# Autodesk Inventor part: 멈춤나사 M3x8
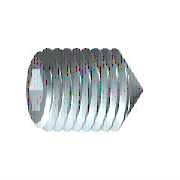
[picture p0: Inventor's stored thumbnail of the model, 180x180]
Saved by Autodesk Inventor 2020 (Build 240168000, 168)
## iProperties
Created: 2012-02
Part Number: 멈춤나사 M3x8
Material: 강철, 연강
Description: 6각 소켓 머리 없는 멈춤 나사
Document SubType Name: Modeling
Standard: KS B 1028
Designer: mduedu
Standards Organization: KS
Language: ko-KR
Size Designation: 원추점 M3x8
Categories: <MemberInstance><Categories><Category DisplayName="조임쇠" InternalName="e4da775c-781d-43d5-af7c-5136215cf5a6" Mnemonic="FSTN"><Category DisplayName="볼트" InternalN
Density: 7.86 g/cm^3
Mass: 0.360339 g
Surface Area: 0.888172 cm^2
Volume: 0.0458447 cm^3
Appearance: 강철
IsCustomPart: 1
Author: mduedu
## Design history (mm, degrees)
sketch "스케치1"
  geometry: L1 (0, 0)-(5.5, 0); L2 (8, 0.866)-(8, 1.5); L3 (8, 1.5)-(0, 1.5); L4 (8, 0.866)-(6, 0.866); L5 (6, 0.866)-(5.5, 0); L6 (0, -0.3)-(0, 1.8) reference; L7 (0, 1.5)-(0, 0)
  constraints: 13 end point, 3 parallel, 1 collinear, 1 perpendicular, 1 point on line
  dimensions: "d0" = 2 distance of L2.start L4.end (= INTI); "d1" = 60 deg angle of L5 L1; "d2" = 3 diameter of L3 L1 (= NND); "d3" = 1.73205 diameter of L4 L1 (= 1.1547 x SW); "d5" = 8 distance from line of L2 L3.end (= NLG)
revolve "본체" sketch "스케치1" stored, may be unused: angle "d6" = 90 deg
sketch "스케치2"
  geometry: L1 (-0.433, 0.75)-(0.433, 0.75); L2 (0.433, 0.75)-(0.866, 0); L3 (0.866, 0)-(0.433, -0.75); L4 (0.433, -0.75)-(-0.433, -0.75); L5 (-0.433, -0.75)-(-0.866, 0); L6 (-0.866, 0)-(-0.433, 0.75); 3 further points
  constraints: 12 end point, 1 coincident, 1 horizontal, 13 other
extrude "슬롯" join sketch "스케치2" taper "d7" = 0 deg; stored distance "d21" = 10
workaxis "Work Axis1"
workplane "Work Plane1"
sketch "스케치5"
  geometry: L1 (-4, -0.15)-(-2.65, -1.5) reference; L2 (-4, 0.15)-(-2.65, 1.5) reference; L3 (-2.65, 1.5)-(-4.15, 0); L4 (-2.65, -1.5)-(-4.15, 0); 1 further point
  constraints: 4 end point, 1 horizontal alignment, 1 perpendicular
node "작업점1"
body "Solid1"
feature "스레드" dims "d12" = 8 (= NLG), "d13" = 0
chamfer "모따기1" distance "d8" = 1.35 (computed from NND, SPD, FAWI); stored, may be unused: angle "d9" = 45 deg (= FAWI), second distance "d34" = 1.35 (computed from NND, SPD, FAWI)
chamfer "모따기2" distance "d10" = 0.30673 (= -0.5 x GD1 + 0.5 x NND); stored, may be unused: angle "d11" = 45 deg (= FAWI), second distance "d35" = 0.30673 (= -0.5 x GD1 + 0.5 x NND)
other parameters: "NND" = 3 [user parameter; used in 5 equation terms], "NLG" = 8 [user parameter; used in 2 equation terms], "INTI" = 2 [user parameter; used in 1 equation term], "FAWI" = 45 deg [user parameter; used in 4 equation terms], "SW" = 1.5 [user parameter; used in 2 equation terms], "GD1" = 2.38655 (= THREADDIA - 1.2269 x PTC) [user parameter; used in 2 equation terms], "d4" = 0, "FAWI1" = 45 deg [user parameter], "SPD" = 0.3 [user parameter; used in 2 equation terms], "d36" = 0, "d37" = 0, "GUL" = 0.30673 (= 0.61345 x PTC) [user parameter], "TOA" = 30 deg [user parameter], "THREADDIA" = 3 [user parameter; used in 1 equation term], "PTC" = 0.5 [user parameter; used in 4 equation terms], "GAL" = 0.30673 (= 0.61345 x PTC) [user parameter], "E0" = 1.7325 (= 1.155 x SW) [user parameter]
